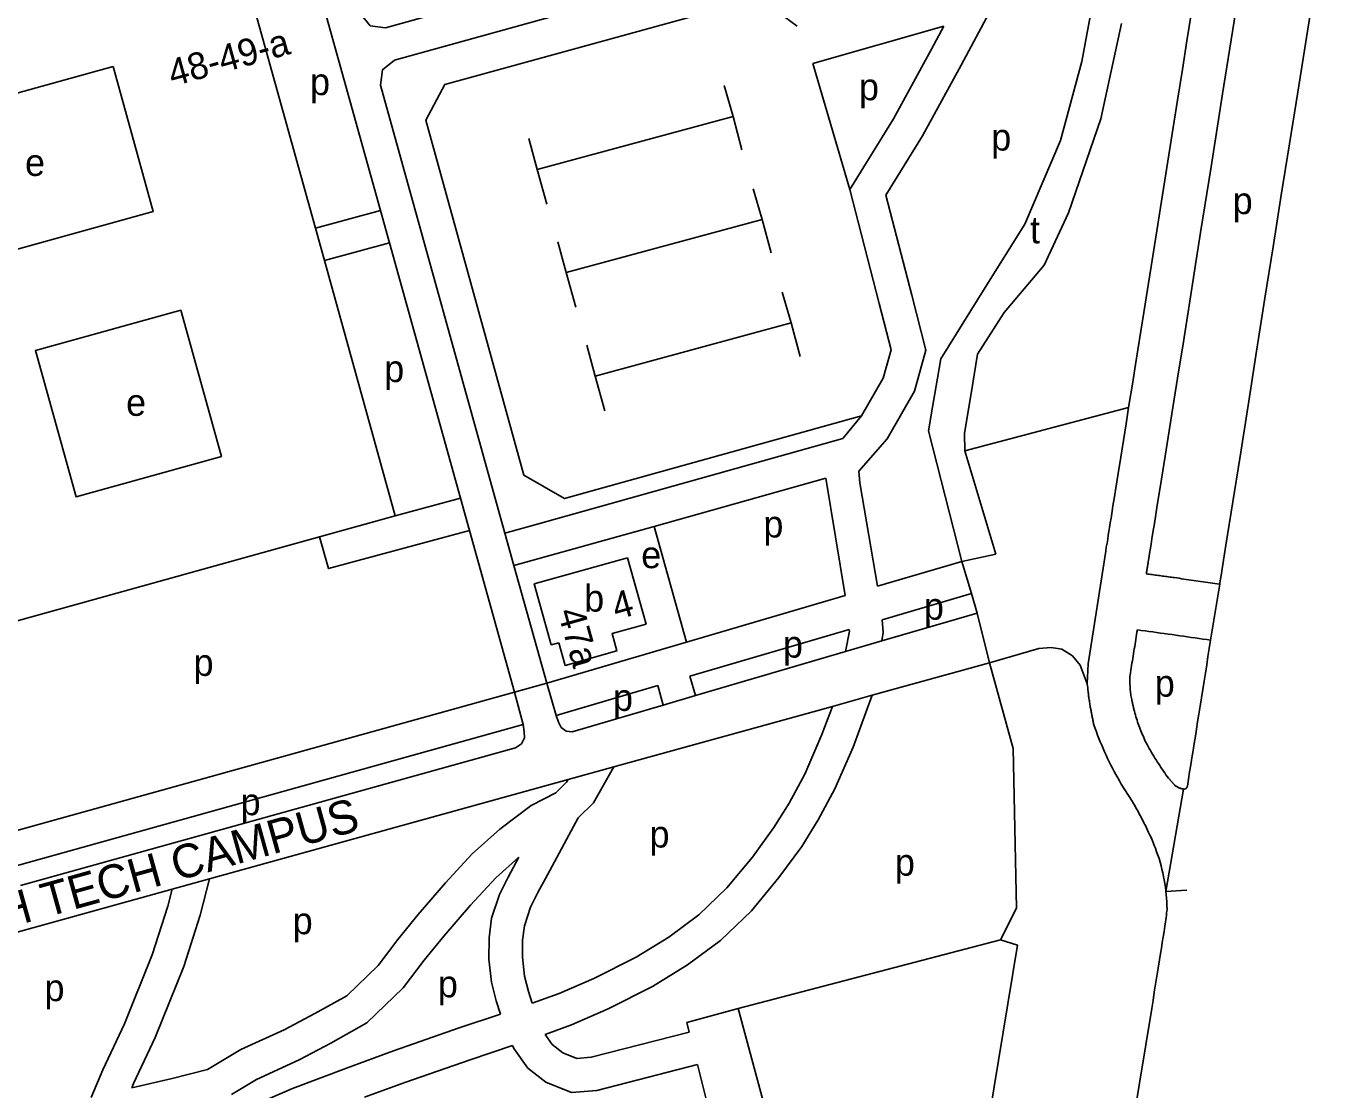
# Model space of a CAD drawing. Extents: x 158358 to 160383, y 379531 to 380764.
# Drawn here: x 160128 to 160322.5, y 380237.9 to 380396.2 of the extents above; entities that cross this region are included whole.
import ezdxf

# ---------------------------------------------------------------- set-up
doc = ezdxf.new("R2010")
doc.units = 0
for name, color, linetype in [('BLT_Basislijn', 7, 'Continuous'), ('BLT_Bebouwing', 7, 'Continuous'), ('BLT_Centroide', 7, 'Continuous'), ('BLT_Huisnummer_reeks', 7, 'Continuous'), ('BLT_Straatnaam', 7, 'Continuous'), ('BLT_Vlakafsluiter', 7, 'Continuous')]:
    doc.layers.add(name, color=color, linetype=linetype)

msp = doc.modelspace()

# ---------------------------------------------------------------- linework, layer by layer
at = {"layer": 'BLT_Basislijn'}
for p, q in [((160286.85, 380400.36), (160285.14, 380390.94)), ((160264.59, 380396.17), (160245.11, 380390.63)), ((160287.96, 380382.4), (160291.06, 380396.6)), ((160285.14, 380390.94), (160281.98, 380379.19)), ((160245.11, 380390.63), (160250.58, 380371.86)), ((160231.89, 380387.33), (160233.23, 380382.75)), ((160204.06, 380374.84), (160233.23, 380382.75)), ((160233.23, 380382.75), (160234.55, 380377.77)), ((160283.16, 380368.41), (160287.96, 380382.4)), ((160204.06, 380374.84), (160202.8, 380379.44)), ((160281.98, 380379.19), (160276.65, 380366.7)), ((160204.06, 380374.84), (160205.48, 380369.68)), ((160236.23, 380371.99), (160237.56, 380367.41)), ((160180.74, 380368.74), (160171.05, 380366.13)), ((160279.53, 380360.62), (160283.16, 380368.41)), ((160208.39, 380359.5), (160237.56, 380367.41)), ((160237.56, 380367.41), (160238.89, 380362.43)), ((160276.65, 380366.7), (160270.77, 380357.31)), ((160182.08, 380363.92), (160172.39, 380361.31)), ((160208.39, 380359.5), (160207.13, 380364.1)), ((160273.55, 380353.57), (160279.53, 380360.62)), ((160208.39, 380359.5), (160209.81, 380354.35)), ((160240.54, 380356.59), (160241.88, 380352.01)), ((160270.77, 380357.31), (160264.14, 380346.69)), ((160212.71, 380344.1), (160241.88, 380352.01)), ((160241.88, 380352.01), (160243.2, 380347.02)), ((160269.6, 380347.37), (160273.55, 380353.57)), ((160212.71, 380344.1), (160211.45, 380348.69)), ((160264.14, 380346.69), (160262.98, 380339.79)), ((160268.64, 380341.5), (160269.6, 380347.37)), ((160212.71, 380344.1), (160214.13, 380338.94)), ((160267.68, 380335.63), (160268.64, 380341.5)), ((160262.98, 380339.79), (160262.33, 380335.95)), ((160267.72, 380333), (160292.1, 380339.45)), ((160249.57, 380334.83), (160252.36, 380338.2)), ((160204.25, 380322.12), (160249.57, 380334.83)), ((160262.33, 380335.95), (160267.28, 380316.53)), ((160267.72, 380333), (160267.68, 380335.63)), ((160272.31, 380317.59), (160267.72, 380333)), ((160221.49, 380321.7), (160247.01, 380328.92)), ((160249.91, 380311.44), (160247.01, 380328.92)), ((160182.95, 380323.32), (160192.64, 380325.93)), ((160221.49, 380321.7), (160226.27, 380304.5)), ((160267.28, 380316.53), (160272.31, 380317.59)), ((160254.74, 380312.85), (160267.28, 380316.53)), ((160268.69, 380311.73), (160267.28, 380316.53)), ((160226.27, 380304.5), (160249.91, 380311.44)), ((160255.39, 380307.83), (160268.69, 380311.73)), ((160268.69, 380311.73), (160269.53, 380308.85)), ((160269.53, 380308.85), (160271.4, 380301.43)), ((160226.81, 380299.45), (160250.51, 380306.4)), ((160205.48, 380298.4), (160226.27, 380304.5)), ((160226.81, 380299.45), (160227.61, 380296.55)), ((160206.89, 380293.6), (160205.48, 380298.4)), ((160206.89, 380293.6), (160222.01, 380298.04)), ((160222.01, 380298.04), (160222.81, 380295.14)), ((160124.46, 380275.87), (160200.67, 380297.06)), ((160200.67, 380297.06), (160202, 380292.24)), ((160126.15, 380271.15), (160202, 380292.24)), ((160295.54, 380250), (160287.26, 380199.97))]:
    msp.add_line(p, q, dxfattribs=at)
for points in [[(160171.69, 380419.99), (160177.79, 380398.02), (160179.21, 380396.21), (160181.49, 380395.93), (160230, 380409.42)], [(160305.66, 380313.16), (160305.67, 380313.26), (160305.69, 380313.36), (160305.86, 380314.43), (160306.13, 380316.08), (160306.59, 380318.93), (160307.61, 380325.38), (160308.63, 380331.83), (160309.87, 380339.71), (160311.14, 380347.8), (160312.38, 380355.68), (160313.6, 380363.35), (160314.82, 380371.02), (160316.05, 380378.69), (160317.28, 380386.36), (160318.92, 380396.68), (160320.7, 380407.88), (160321.91, 380415.55), (160322.21, 380417.32), (160322.5, 380419.08)], [(160169.94, 380407.59), (160180.74, 380368.74)], [(160240.21, 380407.06), (160182.83, 380391.11), (160181.02, 380389.7), (160180.74, 380387.42), (160199.27, 380320.75)], [(160309.53, 380407.78), (160307.81, 380396.94), (160306.09, 380386.09), (160304.37, 380375.25), (160302.82, 380365.49), (160301.96, 380360.06), (160301.11, 380354.63), (160300.25, 380349.19), (160299.39, 380343.8), (160298.53, 380338.48), (160297.67, 380333.15), (160296.82, 380327.82), (160296.35, 380324.88), (160296.14, 380323.53), (160295.93, 380322.18), (160295.72, 380320.83), (160295.57, 380319.9), (160295.44, 380319.08), (160295.31, 380318.26), (160295.17, 380317.43)], [(160242.74, 380396.2), (160237.13, 380400.38), (160190.32, 380387.51), (160187.5, 380382.17), (160202.09, 380329.35), (160208.12, 380325.88), (160252.36, 380338.2)], [(160292.1, 380339.45), (160292.71, 380343.22), (160292.92, 380344.53), (160293.14, 380345.83), (160293.49, 380347.99), (160294.38, 380353.59), (160295.27, 380359.18), (160296.16, 380364.78), (160297.01, 380370.13), (160297.8, 380375.14), (160298.59, 380380.14), (160299.38, 380385.15), (160300.1, 380389.71), (160300.78, 380393.98), (160301.46, 380398.24), (160301.82, 380400.5)], [(160255.96, 380371.05), (160261.44, 380379.86), (160267.16, 380390.37), (160271.27, 380398.07)], [(160250.58, 380371.86), (160257.12, 380382.38), (160262.76, 380392.74), (160264.59, 380396.17)], [(160252.36, 380338.2), (160255.58, 380343.79), (160256.74, 380348.01), (160254.99, 380354.92), (160250.58, 380371.86)], [(160251.94, 380329.94), (160256.16, 380334.79), (160260.23, 380341.85), (160261.91, 380347.96), (160259.83, 380356.16), (160255.96, 380371.05)], [(160180.74, 380368.74), (160182.08, 380363.92)], [(160182.08, 380363.92), (160192.64, 380325.93)], [(160292.1, 380339.45), (160291.71, 380336.99), (160291.32, 380334.52), (160290.93, 380332.06), (160290.53, 380329.59), (160290.14, 380327.13), (160289.94, 380325.83), (160289.82, 380325.11), (160289.71, 380324.4), (160289.6, 380323.68), (160289.48, 380322.97), (160289.37, 380322.25), (160289.26, 380321.58), (160289.17, 380320.99), (160289.07, 380320.41), (160288.98, 380319.82), (160288.88, 380319.24), (160288.78, 380318.65), (160288.69, 380318.07)], [(160254.74, 380312.85), (160252.1, 380328.21), (160251.94, 380329.94)], [(160192.64, 380325.93), (160193.98, 380321.11)], [(160171.69, 380320.19), (160172.99, 380315.46), (160193.98, 380321.11)], [(160193.98, 380321.11), (160200.67, 380297.06)], [(160199.27, 380320.75), (160204.25, 380322.12)], [(160200.61, 380315.93), (160221.49, 380321.7)], [(160199.27, 380320.75), (160200.61, 380315.93)], [(160294.97, 380316.12), (160294.98, 380316.19), (160294.99, 380316.26), (160295, 380316.33), (160295.01, 380316.4), (160295.02, 380316.47), (160295.03, 380316.54), (160295.04, 380316.6), (160295.05, 380316.67), (160295.06, 380316.74), (160295.08, 380316.81), (160295.09, 380316.88), (160295.1, 380316.95), (160295.11, 380317.02), (160295.12, 380317.09), (160295.13, 380317.16), (160295.14, 380317.23), (160295.15, 380317.3), (160295.16, 380317.37), (160295.17, 380317.43)], [(160200.61, 380315.93), (160205.48, 380298.4)], [(160294.97, 380316.12), (160294.95, 380316.04), (160294.94, 380315.97), (160294.93, 380315.89), (160294.92, 380315.82), (160294.9, 380315.74), (160294.89, 380315.67), (160294.88, 380315.59), (160294.87, 380315.51), (160294.85, 380315.44), (160294.84, 380315.36), (160294.83, 380315.29), (160294.81, 380315.21), (160294.8, 380315.14), (160294.79, 380315.06), (160294.78, 380314.98), (160294.76, 380314.91), (160294.75, 380314.83), (160294.74, 380314.76), (160294.73, 380314.68)], [(160294.73, 380314.68), (160294.94, 380314.65), (160295.16, 380314.62), (160295.38, 380314.59), (160295.6, 380314.56), (160295.82, 380314.53), (160296.04, 380314.5), (160296.26, 380314.47), (160296.48, 380314.44), (160296.7, 380314.41), (160296.92, 380314.38), (160297.14, 380314.35), (160297.36, 380314.32), (160297.58, 380314.29), (160297.8, 380314.26), (160298.02, 380314.23), (160298.24, 380314.2), (160298.46, 380314.17), (160298.68, 380314.14), (160298.9, 380314.11)], [(160298.9, 380314.11), (160299.26, 380314.06), (160299.61, 380314.01), (160299.97, 380313.96), (160300.32, 380313.91), (160300.68, 380313.86), (160301.03, 380313.81), (160301.39, 380313.76), (160301.75, 380313.71), (160302.1, 380313.66), (160302.46, 380313.61), (160302.81, 380313.56), (160303.17, 380313.51), (160303.52, 380313.46), (160303.88, 380313.41), (160304.24, 380313.36), (160304.59, 380313.31), (160304.95, 380313.26), (160305.3, 380313.21), (160305.66, 380313.16)], [(160255.35, 380304.69), (160269.53, 380308.85)], [(160255.35, 380304.69), (160255.58, 380305.96), (160255.39, 380307.83)], [(160249.98, 380303.12), (160250.54, 380306.15), (160250.51, 380306.4)], [(160293.4, 380306.35), (160293.34, 380306), (160293.28, 380305.64), (160293.23, 380305.29), (160293.17, 380304.93), (160293.11, 380304.58), (160293.05, 380304.22), (160293, 380303.87), (160292.94, 380303.51), (160292.88, 380303.16), (160292.83, 380302.8), (160292.77, 380302.45), (160292.71, 380302.09), (160292.66, 380301.74), (160292.6, 380301.38), (160292.54, 380301.03), (160292.49, 380300.67), (160292.43, 380300.32), (160292.37, 380299.96), (160292.32, 380299.61)], [(160304.3, 380304.82), (160303.72, 380304.9), (160303.15, 380304.98), (160302.58, 380305.06), (160302, 380305.14), (160301.43, 380305.22), (160300.85, 380305.3), (160300.28, 380305.38), (160299.71, 380305.46), (160299.13, 380305.55), (160298.56, 380305.63), (160297.99, 380305.71), (160297.41, 380305.79), (160296.84, 380305.87), (160296.26, 380305.95), (160295.69, 380306.03), (160295.12, 380306.11), (160294.54, 380306.19), (160293.97, 380306.27), (160293.4, 380306.35)], [(160249.98, 380303.12), (160255.35, 380304.69)], [(160271.4, 380301.43), (160278.73, 380303.56), (160280.56, 380303.74), (160282.18, 380303.46), (160283.72, 380302.5), (160284.9, 380301.11), (160285.95, 380298.33)], [(160300.84, 380283.07), (160301.01, 380284.13), (160301.18, 380285.2), (160301.35, 380286.26), (160301.52, 380287.32), (160301.69, 380288.39), (160301.86, 380289.45), (160302.03, 380290.52), (160302.2, 380291.58), (160302.37, 380292.64), (160302.56, 380293.79), (160302.75, 380295.01), (160302.94, 380296.24), (160303.14, 380297.46), (160303.33, 380298.69), (160303.52, 380299.92), (160303.72, 380301.14), (160303.91, 380302.37), (160304.1, 380303.59), (160304.3, 380304.82)], [(160227.61, 380296.55), (160249.98, 380303.12)], [(160253.95, 380296.6), (160271.4, 380301.43)], [(160271.4, 380301.43), (160274.92, 380288.71), (160275.43, 380264.92), (160273.02, 380260.23)], [(160292.32, 380299.61), (160292.3, 380299.4), (160292.3, 380299.2), (160292.29, 380299), (160292.29, 380298.8), (160292.29, 380298.59), (160292.29, 380298.39), (160292.3, 380298.19), (160292.31, 380297.98), (160292.32, 380297.78), (160292.33, 380297.58), (160292.35, 380297.38), (160292.37, 380297.17), (160292.4, 380296.97), (160292.42, 380296.77), (160292.45, 380296.57), (160292.48, 380296.37), (160292.52, 380296.17), (160292.56, 380295.97), (160292.6, 380295.77)], [(160286.39, 380294.85), (160286.36, 380295.03), (160286.34, 380295.21), (160286.31, 380295.4), (160286.28, 380295.58), (160286.25, 380295.76), (160286.23, 380295.94), (160286.2, 380296.13), (160286.18, 380296.31), (160286.15, 380296.49), (160286.13, 380296.67), (160286.11, 380296.86), (160286.09, 380297.04), (160286.07, 380297.22), (160286.04, 380297.41), (160286.02, 380297.59), (160286.01, 380297.77), (160285.99, 380297.96), (160285.95, 380298.33)], [(160205.24, 380246.15), (160209.19, 380247.56), (160214.63, 380249.93), (160221.23, 380253.26), (160226.45, 380256.47), (160231.35, 380260.12), (160235.97, 380264.52), (160240.05, 380269.48), (160243.45, 380274.12), (160245.9, 380278.07), (160248.39, 380282.7), (160251.09, 380288.89), (160253.95, 380296.6)], [(160222.81, 380295.14), (160227.61, 380296.55)], [(160248, 380294.95), (160253.95, 380296.6)], [(160292.6, 380295.77), (160292.6, 380295.76), (160292.6, 380295.76), (160292.6, 380295.75), (160292.6, 380295.74), (160292.61, 380295.74), (160292.61, 380295.73), (160292.61, 380295.72), (160292.61, 380295.71), (160292.61, 380295.71), (160292.63, 380295.64), (160292.66, 380295.51), (160292.69, 380295.38), (160292.71, 380295.25), (160292.74, 380295.12), (160292.77, 380295), (160292.8, 380294.87), (160292.83, 380294.74), (160292.85, 380294.61), (160292.88, 380294.48)], [(160203.31, 380250.77), (160207.35, 380252.22), (160212.51, 380254.46), (160218.79, 380257.63), (160223.64, 380260.61), (160228.12, 380263.95), (160232.31, 380267.93), (160236.1, 380272.54), (160239.3, 380276.92), (160241.57, 380280.57), (160243.89, 380284.89), (160246.45, 380290.76), (160248, 380294.95)], [(160206.89, 380293.6), (160207.23, 380292.62), (160207.65, 380291.83), (160208.37, 380291.25), (160209.27, 380291.17), (160222.81, 380295.14)], [(160215.47, 380285.94), (160248, 380294.95)], [(160286.92, 380292.2), (160286.89, 380292.34), (160286.86, 380292.48), (160286.83, 380292.62), (160286.8, 380292.76), (160286.78, 380292.9), (160286.75, 380293.04), (160286.72, 380293.18), (160286.69, 380293.31), (160286.66, 380293.45), (160286.64, 380293.59), (160286.61, 380293.73), (160286.58, 380293.87), (160286.56, 380294.01), (160286.53, 380294.15), (160286.5, 380294.29), (160286.47, 380294.43), (160286.45, 380294.57), (160286.42, 380294.71), (160286.39, 380294.85)], [(160292.88, 380294.48), (160292.96, 380294.22), (160293.03, 380293.95), (160293.11, 380293.68), (160293.19, 380293.42), (160293.27, 380293.15), (160293.35, 380292.89), (160293.44, 380292.63), (160293.53, 380292.37), (160293.63, 380292.1), (160293.72, 380291.84), (160293.82, 380291.58), (160293.92, 380291.33), (160294.02, 380291.07), (160294.13, 380290.81), (160294.24, 380290.56), (160294.35, 380290.3), (160294.46, 380290.05), (160294.58, 380289.8), (160294.69, 380289.55)], [(160127.16, 380268.32), (160200.86, 380288.81), (160201.73, 380289.38), (160202.17, 380290.25), (160202.15, 380291.19), (160202, 380292.24)], [(160292.62, 380280.83), (160291.01, 380283.4), (160290.74, 380283.87), (160290.47, 380284.33), (160290.21, 380284.8), (160289.95, 380285.28), (160289.7, 380285.75), (160289.45, 380286.23), (160289.21, 380286.72), (160288.97, 380287.2), (160288.74, 380287.69), (160288.52, 380288.18), (160288.3, 380288.68), (160288.09, 380289.17), (160287.88, 380289.67), (160287.68, 380290.17), (160287.49, 380290.67), (160287.3, 380291.18), (160287.12, 380291.68), (160286.92, 380292.2)], [(160294.69, 380289.55), (160294.85, 380289.26), (160295.01, 380288.97), (160295.17, 380288.68), (160295.34, 380288.4), (160295.51, 380288.11), (160295.67, 380287.83), (160295.85, 380287.55), (160296.02, 380287.27), (160296.19, 380286.99), (160296.37, 380286.71), (160296.55, 380286.43), (160296.73, 380286.15), (160296.91, 380285.88), (160297.09, 380285.6), (160297.28, 380285.33), (160297.47, 380285.06), (160297.66, 380284.79), (160297.85, 380284.52), (160298.04, 380284.25)], [(160208.67, 380284.06), (160215.47, 380285.94)], [(160210.17, 380278.35), (160212.46, 380280.59), (160215.47, 380285.94)], [(160143.71, 380238.19), (160149.72, 380239.57), (160155.01, 380240.91), (160159.95, 380243.87), (160166.41, 380246.83), (160170.98, 380249.24), (160175.72, 380251.9), (160180.39, 380256.4), (160183.33, 380260.26), (160186.36, 380263.97), (160190.4, 380268.7), (160194.4, 380273), (160198.51, 380276.7), (160203.19, 380280.21), (160206.84, 380282.09), (160208.45, 380283.66), (160208.67, 380284.06)], [(160155.31, 380269.28), (160208.67, 380284.06)], [(160298.04, 380284.25), (160298.08, 380284.2), (160298.13, 380284.15), (160298.17, 380284.1), (160298.21, 380284.05), (160298.26, 380284.01), (160298.3, 380283.96), (160298.34, 380283.91), (160298.39, 380283.86), (160298.43, 380283.81), (160298.47, 380283.76), (160298.52, 380283.71), (160298.56, 380283.66), (160298.61, 380283.61), (160298.65, 380283.56), (160298.69, 380283.51), (160298.74, 380283.46), (160298.78, 380283.41), (160298.82, 380283.37), (160298.87, 380283.32)], [(160298.87, 380283.32), (160298.93, 380283.26), (160298.99, 380283.21), (160299.05, 380283.15), (160299.12, 380283.1), (160299.18, 380283.06), (160299.25, 380283.01), (160299.32, 380282.97), (160299.4, 380282.92), (160299.47, 380282.89), (160299.55, 380282.85), (160299.62, 380282.82), (160299.7, 380282.79), (160299.78, 380282.76), (160299.86, 380282.73), (160299.94, 380282.71), (160300.02, 380282.69), (160300.1, 380282.68), (160300.18, 380282.66), (160300.26, 380282.65)], [(160300.26, 380282.65), (160300.3, 380282.65), (160300.34, 380282.65), (160300.38, 380282.65), (160300.42, 380282.65), (160300.46, 380282.66), (160300.5, 380282.67), (160300.54, 380282.69), (160300.58, 380282.71), (160300.62, 380282.73), (160300.65, 380282.75), (160300.69, 380282.78), (160300.72, 380282.81), (160300.74, 380282.85), (160300.77, 380282.88), (160300.79, 380282.92), (160300.81, 380282.96), (160300.82, 380282.99), (160300.83, 380283.03), (160300.84, 380283.07)], [(160295.96, 380274.14), (160295.53, 380275.18), (160295.38, 380275.53), (160295.23, 380275.87), (160295.07, 380276.21), (160294.91, 380276.55), (160294.75, 380276.88), (160294.59, 380277.22), (160294.42, 380277.55), (160294.26, 380277.89), (160294.08, 380278.22), (160293.91, 380278.55), (160293.73, 380278.88), (160293.56, 380279.21), (160293.37, 380279.54), (160293.19, 380279.86), (160293, 380280.19), (160292.81, 380280.51), (160292.62, 380280.83)], [(160210.17, 380278.35), (160205.59, 380269.88), (160204.18, 380267.26), (160203.09, 380265.06), (160202.16, 380262.3), (160201.9, 380260.16), (160201.87, 380257.61), (160202.2, 380254.82), (160202.77, 380252.51), (160203.31, 380250.77)], [(160158.56, 380237.21), (160162.29, 380239.44), (160168.62, 380242.34), (160173.37, 380244.84), (160178.72, 380247.85), (160184.14, 380253.06), (160187.26, 380257.17), (160190.19, 380260.77), (160194.13, 380265.37), (160197.91, 380269.43), (160201.34, 380272.53)], [(160201.34, 380272.53), (160199.74, 380269.56), (160198.46, 380266.97), (160197.26, 380263.42), (160196.9, 380260.49), (160196.87, 380257.35), (160197.27, 380253.92), (160197.95, 380251.16), (160198.59, 380249.14)], [(160297.66, 380267.4), (160297.65, 380267.5), (160297.58, 380268.04), (160297.5, 380268.58), (160297.4, 380269.12), (160297.3, 380269.66), (160297.19, 380270.19), (160297.06, 380270.72), (160296.92, 380271.25), (160296.78, 380271.77), (160296.62, 380272.3), (160296.45, 380272.81), (160296.27, 380273.33), (160296.08, 380273.84), (160295.96, 380274.14)], [(160143.71, 380238.19), (160143.98, 380238.84), (160147.2, 380245.69), (160151.48, 380256.26), (160153.91, 380263.86), (160155.31, 380269.28)], [(160149.75, 380267.74), (160155.31, 380269.28)], [(160097.49, 380253.26), (160149.75, 380267.74)], [(160137.7, 380236.73), (160139.4, 380240.86), (160142.62, 380247.7), (160146.78, 380257.96), (160149.11, 380265.24), (160149.75, 380267.74)], [(160297.83, 380264.8), (160297.81, 380265.34), (160297.79, 380265.88), (160297.75, 380266.42), (160297.71, 380266.96), (160297.66, 380267.4)], [(160295.54, 380250), (160295.73, 380251.2), (160295.92, 380252.41), (160296.11, 380253.61), (160296.31, 380254.82), (160296.5, 380256.02), (160296.69, 380257.23), (160296.85, 380258.17), (160296.98, 380258.99), (160297.11, 380259.8), (160297.24, 380260.62), (160297.37, 380261.43), (160297.51, 380262.25), (160297.61, 380262.89), (160297.64, 380263.21), (160297.68, 380263.53), (160297.72, 380263.85), (160297.75, 380264.16), (160297.79, 380264.48), (160297.83, 380264.8)], [(160234, 380250), (160273.02, 380260.23)], [(160273.02, 380260.23), (160275.56, 380259.4), (160247.94, 380091.73)], [(160153.94, 380229.81), (160156.56, 380231.76), (160160.99, 380234.89), (160164.33, 380236.67), (160167.63, 380238.1), (160175.67, 380241.12), (160182.7, 380243.7), (160192.47, 380247.11), (160198.59, 380249.14)], [(160176.4, 380200.53), (160177.79, 380194.61), (160243.96, 380213.05), (160234, 380250)], [(160226.71, 380246.49), (160226.35, 380247.91), (160234, 380250)], [(160205.24, 380246.15), (160206.32, 380244.62), (160207.87, 380243.41), (160209.98, 380242.57), (160212.12, 380242.73), (160226.71, 380246.49)], [(160178.34, 380236.78), (160184.38, 380238.99), (160194.08, 380242.38), (160200.4, 380244.47)], [(160200.4, 380244.47), (160200.61, 380244.05), (160202.66, 380241.13), (160205.36, 380239.03), (160209.19, 380237.5), (160212.93, 380237.77), (160227.93, 380241.64)], [(160205.08, 380208.8), (160234.08, 380217.08), (160227.93, 380241.64)]]:
    msp.add_lwpolyline(points, dxfattribs=at)
at = {"layer": 'BLT_Bebouwing'}
for points in [[(160160.25, 380404.99), (160171.05, 380366.13)], [(160140.93, 380390.19), (160112.1, 380382.2), (160118.1, 380360.6), (160146.93, 380368.58), (160140.93, 380390.19)], [(160171.05, 380366.13), (160172.39, 380361.31)], [(160172.39, 380361.31), (160182.95, 380323.32)], [(160151.02, 380353.91), (160129.39, 380347.91), (160135.44, 380326.15), (160157.07, 380332.16), (160151.02, 380353.91)], [(160182.95, 380323.32), (160171.69, 380320.19)], [(160171.69, 380320.19), (160117.53, 380305.15)], [(160217.53, 380317.08), (160203.62, 380313.21), (160206.16, 380304.12), (160207.28, 380304.43)], [(160220.29, 380307.21), (160217.53, 380317.08)], [(160207.28, 380304.43), (160208.22, 380301.06), (160215.94, 380303.21), (160215.22, 380305.79), (160220.29, 380307.21)]]:
    msp.add_lwpolyline(points, dxfattribs=at)
at = {"layer": 'BLT_Vlakafsluiter'}
for p, q in [((160305.66, 380313.16), (160304.3, 380304.82)), ((160200.67, 380297.06), (160205.48, 380298.4)), ((160297.66, 380267.4), (160300.26, 380282.65)), ((160300.74, 380267.61), (160297.66, 380267.4))]:
    msp.add_line(p, q, dxfattribs=at)
msp.add_lwpolyline([(160288.69, 380318.07), (160286.06, 380301.3), (160285.95, 380298.33)], dxfattribs=at)

# ---------------------------------------------------------------- texts
at = {"layer": 'BLT_Centroide'}
for s, p in [('p', (160170.26, 380385.92)), ('p', (160251.96, 380385.16)), ('p', (160271.65, 380377.67)), ('e', (160127.84, 380373.89)), ('p', (160307.59, 380368.21)), ('t', (160277.43, 380363.86)), ('p', (160181.3, 380343.22)), ('e', (160142.88, 380338.19)), ('p', (160237.74, 380320.09)), ('e', (160219.55, 380315.52)), ('b', (160211.06, 380309.06)), ('p', (160261.63, 380307.85)), ('p', (160240.65, 380302.21)), ('p', (160152.92, 380299.49)), ('p', (160295.99, 380296.4)), ('p', (160215.35, 380294.28)), ('p', (160159.92, 380278.76)), ('p', (160220.79, 380273.95)), ('p', (160257.31, 380269.76)), ('p', (160167.68, 380261.05)), ('p', (160189.29, 380251.66)), ('p', (160130.73, 380251.09))]:
    msp.add_text(s, height=4, dxfattribs=at).set_placement(p)
at = {"layer": 'BLT_Huisnummer_reeks'}
for s, rotation, p in [('48-49-a', 15.4903, (160149.78, 380387.17)), ('4', 15.6135, (160215.85, 380307.81)), ('47a', 285.5936, (160207.08, 380309.04))]:
    msp.add_text(s, height=4, rotation=rotation, dxfattribs=at).set_placement(p)
at = {"layer": 'BLT_Straatnaam'}
msp.add_text('HIGH TECH CAMPUS', height=5, rotation=15.534, dxfattribs=at).set_placement((160113.14, 380258.59))

doc.saveas('drawing.dxf')
